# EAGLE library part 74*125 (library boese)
Quad BUS SWITCH
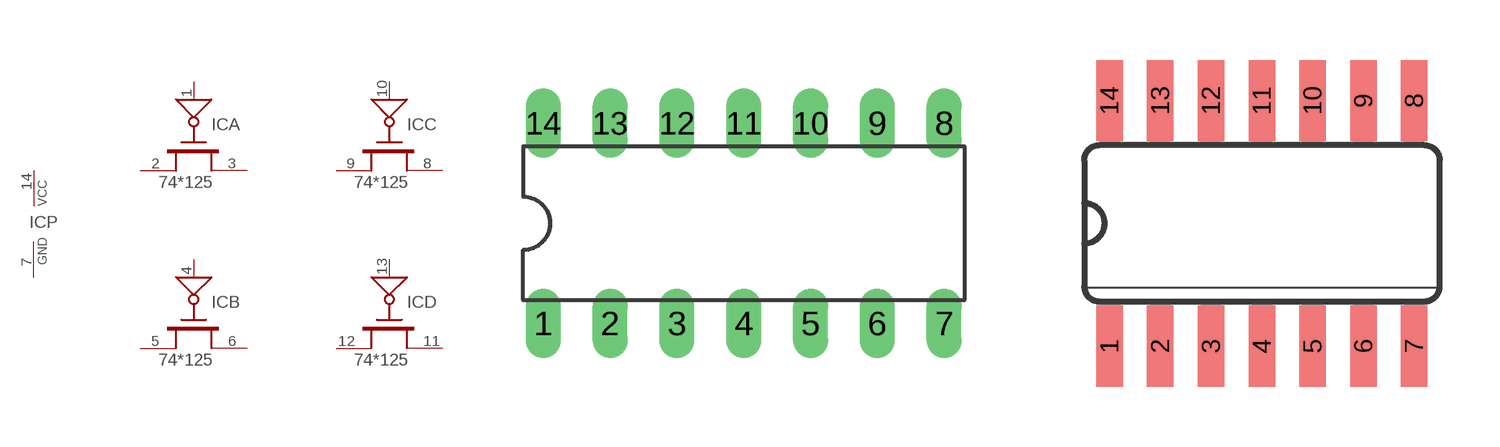
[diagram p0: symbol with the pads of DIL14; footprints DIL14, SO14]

Designator prefix IC; gates A=74*3125 B=74*3125 C=74*3125 D=74*3125 P=PWRN

## 74125N, 74CBTLV125N  [DIL14]
1  A:OE  in
2  A:I
3  A:O
4  B:OE  in
5  B:I
6  B:O
7  P:GND  pwr
8  C:O
9  C:I
10  C:OE  in
11  D:O
12  D:I
13  D:OE  in
14  P:VCC  pwr

## 74125D, 74CBTLV125D  [SO14]
Pads as for DIL14

## Footprint DIL14 (pad centres in mm)
Dual In Line Package
drill 0.813 long: 1 -7.62,-3.81; 2 -5.08,-3.81; 3 -2.54,-3.81; 4 0,-3.81; 5 2.54,-3.81; 6 5.08,-3.81; 7 7.62,-3.81; 8 7.62,3.81; 9 5.08,3.81; 10 2.54,3.81; 11 0,3.81; 12 -2.54,3.81; 13 -5.08,3.81; 14 -7.62,3.81

## Footprint SO14 (pad centres in mm)
Small Outline package 150 mil
smd 0.66 x 2.032: 1 -3.81,-3.073; 2 -2.54,-3.073; 3 -1.27,-3.073; 4 0,-3.073; 5 1.27,-3.073; 6 2.54,-3.073; 7 3.81,-3.073; 8 3.81,3.073; 9 2.54,3.073; 10 1.27,3.073; 11 0,3.073; 12 -1.27,3.073; 13 -2.54,3.073; 14 -3.81,3.073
